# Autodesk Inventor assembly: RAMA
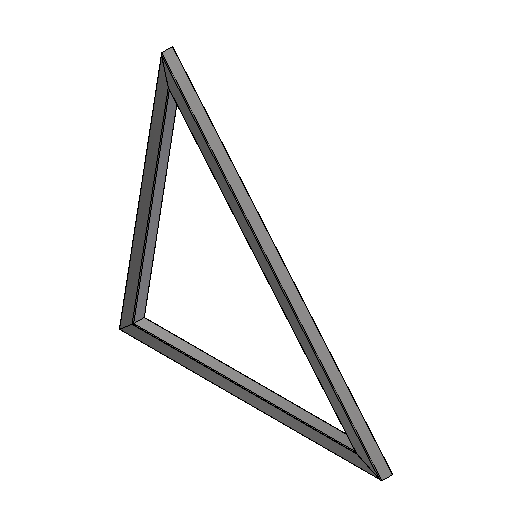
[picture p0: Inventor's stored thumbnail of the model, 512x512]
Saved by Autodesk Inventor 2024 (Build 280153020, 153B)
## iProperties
Created: 2023-03
Part Number: RAMA
Document SubType Name: Assembly
Designer: Andrzej Jaskulski
Checked By: A.J.
Engr Approved By: Andrzej Jaskulski
Mfg Approved By: Andrzej Jaskulski
Authority: A.J.
Company: ATC
_FrameDoc: Frame Assembly
_Version: 25.0.0
Author: Andrzej Jaskulski
Revision Number: 1/24
Title: A.J.: Kurs R2024-MEP
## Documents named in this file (5)
- C:\Users\AndJas\Documents\R2024-MEP\Obszar roboczy\IC-Z-Rama do Kopiowania\Frame\RAMA.iam
- C:\Users\AndJas\Documents\R2024-MEP\Obszar roboczy\IC-Z-Rama do Kopiowania\Frame\SZKIELET.ipt
- C:\Users\AndJas\Documents\R2024-MEP\Obszar roboczy\IC-Z-Rama do Kopiowania\Frame\PN 25 x 25 x 1-1.ipt
- C:\Users\AndJas\Documents\R2024-MEP\Obszar roboczy\IC-Z-Rama do Kopiowania\Frame\PN 25 x 25 x 1-2.ipt
- C:\Users\AndJas\Documents\R2024-MEP\Obszar roboczy\IC-Z-Rama do Kopiowania\Frame\PN 25 x 25 x 1-3.ipt
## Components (4 placed, 2 different names)
1. Model odniesienia ramy
2. PN 25 x 25 x 1:1
3. PN 25 x 25 x 1:2
4. PN 25 x 25 x 1:3
